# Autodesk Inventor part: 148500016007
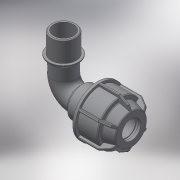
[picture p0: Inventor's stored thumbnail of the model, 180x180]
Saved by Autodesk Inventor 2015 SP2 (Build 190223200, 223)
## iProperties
Created: 2017-08
Part Number: 148500016007
Material: Generic
Description: PLASSON L.14 90° ELBOW MALE ADAPTOR (SILVER) 16-3/4"
Document SubType Name: Modeling
Designer: KIM
Density: 1 g/cm^3
Appearance: Default
Author: KIM
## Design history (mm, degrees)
derived "148500.ipt"
feature "Solid1::148500.ipt"
feature "Solid2::148500.ipt"
tag "TaggingFeature1"
body "Solid1"
body "Solid2"
other parameters: "d1" = 16, "d2" = 43, "d4" = 15 deg, "d5" = 28.38, "d6" = 9.3654, "d10" = 42, "d16" = 16.32, "d17" = 2.15, "d22" = 25.6, "d24" = 2.15, "d25" = 37.8, "d26" = 31.5, "d27" = 2.15, "d28" = 135 deg, "d29" = 1.29, "d31" = 0.8, "d46" = 150 deg, "d49" = 2.1, "d50" = 0, "d58" = 0.48, "d61" = 360 deg, "d63" = 14.4, "d94" = 45, "d96" = 29.0851, "d97" = 18, "d98" = 21.1528, "d99" = 24.72234, "d100" = 135 deg, "d108" = 0.8, "d112" = 23.4, "d113" = 57, "d114" = 43.86, "d115" = 24.72234, "d116" = 45 deg, "d117" = 0, "d118" = 0, "d119" = 26.441, "d120" = 18, "d121" = 31.7292, "d122" = 18.9, "d123" = 1, "d_" = 16, "R_" = 26.441, "E_" = 42, "A_" = 57, "l_" = 43, "l_2" = 18, "A_1" = 45
